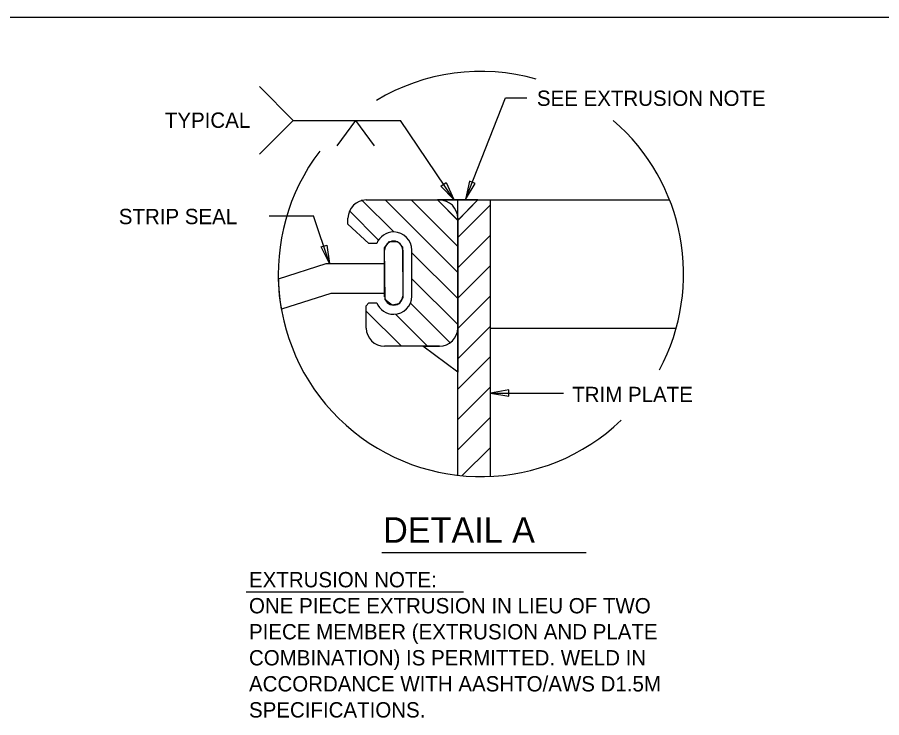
# Model space of a CAD drawing. Extents: x -24512 to -22484, y 4569 to 6351.
# Drawn here: x -23765.7 to -23596.4, y 5603.4 to 5740.6 of the extents above; entities that cross this region are included whole.
import ezdxf

# ---------------------------------------------------------------- set-up
doc = ezdxf.new("R2010")
doc.units = 0
for name, color, linetype in [('10', 7, 'Continuous'), ('2', 7, 'Continuous'), ('4', 7, 'Continuous'), ('9', 7, 'Continuous'), ('PLT-BNDY', 7, 'Continuous')]:
    doc.layers.add(name, color=color, linetype=linetype)

msp = doc.modelspace()

# ---------------------------------------------------------------- linework, layer by layer
at = {"layer": '10'}
for p, q in [((-23691.96, 5698.58), (-23698.29, 5704.91)), ((-23697.35, 5704.85), (-23683.02, 5704.85)), ((-23679.44, 5690.64), (-23693.65, 5704.85)), ((-23679.44, 5695.73), (-23688.56, 5704.85)), ((-23679.44, 5700.88), (-23683.42, 5704.85)), ((-23679.44, 5700.88), (-23675.47, 5704.85)), ((-23694.95, 5697.01), (-23700.64, 5702.7)), ((-23679.44, 5697.52), (-23673.05, 5703.9)), ((-23700.94, 5700.08), (-23700.94, 5701.27)), ((-23679.44, 5701.27), (-23679.44, 5679.77)), ((-23696.87, 5696.34), (-23700.94, 5700.08)), ((-23679.44, 5691.58), (-23673.05, 5697.96)), ((-23695.3, 5696.34), (-23696.87, 5696.34)), ((-23693.77, 5695.49), (-23692.79, 5696.69)), ((-23692.79, 5696.69), (-23691.26, 5696.74)), ((-23691.26, 5696.74), (-23690.23, 5695.65)), ((-23690.23, 5695.65), (-23690.18, 5685.77)), ((-23693.68, 5685.32), (-23693.77, 5695.49)), ((-23688.4, 5686.04), (-23688.4, 5695)), ((-23679.44, 5685.55), (-23688.4, 5694.51)), ((-23714.57, 5689.41), (-23705.18, 5692.4)), ((-23705.18, 5692.4), (-23693.77, 5692.4)), ((-23693.77, 5692.4), (-23693.77, 5686.52)), ((-23679.44, 5685.64), (-23673.05, 5692.03)), ((-23679.44, 5680.46), (-23688.4, 5689.42)), ((-23704.26, 5686.52), (-23713.97, 5683.43)), ((-23693.77, 5686.52), (-23704.26, 5686.52)), ((-23690.18, 5685.77), (-23690.98, 5684.48)), ((-23679.44, 5679.7), (-23673.05, 5686.09)), ((-23697.35, 5684.1), (-23696.87, 5684.7)), ((-23697.35, 5679.77), (-23697.35, 5684.1)), ((-23696.87, 5684.7), (-23695.3, 5684.7)), ((-23692.26, 5684.26), (-23693.68, 5685.32)), ((-23690.98, 5684.48), (-23692.26, 5684.26)), ((-23680.93, 5676.86), (-23688.69, 5684.62)), ((-23690.44, 5676.19), (-23697.35, 5683.1)), ((-23685.35, 5676.19), (-23691.64, 5682.48)), ((-23679.44, 5673.76), (-23673.05, 5680.15)), ((-23679.44, 5679.77), (-23679.44, 5671.12)), ((-23683.02, 5676.19), (-23693.77, 5676.19)), ((-23679.44, 5671.12), (-23686.24, 5676.19)), ((-23686.24, 5676.19), (-23683.02, 5676.19)), ((-23679.44, 5667.82), (-23673.05, 5674.21)), ((-23679.44, 5661.88), (-23673.05, 5668.27)), ((-23679.44, 5655.94), (-23673.05, 5662.33)), ((-23678.6, 5650.84), (-23673.05, 5656.39)), ((-23654.31, 5635.73), (-23694.31, 5635.73)), ((-23678.29, 5628.02), (-23720.86, 5628.02))]:
    msp.add_line(p, q, dxfattribs=at)
msp.add_lwpolyline([(-23713.97, 5683.43), (-23714.35, 5686.17), (-23714.57, 5689.41)], dxfattribs=at)
for centre, radius, start, end in [((-23674.89, 5690.36), 39.69, 74.1716, 121.062), ((-23674.89, 5690.36), 39.69, 331.7898, 49.227), ((-23674.89, 5690.36), 39.69, 142.6924, 313.8219), ((-23697.35, 5701.27), 3.58, 90, 180), ((-23683.02, 5701.27), 3.58, 0, 90), ((-23691.98, 5695), 3.58, 90, 157.9967), ((-23691.98, 5695), 3.58, 0, 90), ((-23691.98, 5686.04), 3.58, 270, 0), ((-23691.98, 5686.04), 3.58, 202.0033, 270), ((-23693.77, 5679.77), 3.58, 180, 270), ((-23683.02, 5679.77), 3.58, 270, 0), ((-23683.02, 5679.77), 3.58, 270, 0)]:
    msp.add_arc(centre, radius, start, end, dxfattribs=at)
at = {"layer": '2'}
msp.add_line((-24137.79, 5740.63), (-23353.75, 5740.63), dxfattribs=at)
at = {"layer": '4'}
for p, q in [((-23684.66, 5704.85), (-23676.71, 5704.85)), ((-23679.44, 5650.93), (-23679.44, 5704.85)), ((-23679.44, 5704.85), (-23637.94, 5704.85)), ((-23673.05, 5650.71), (-23673.05, 5704.85)), ((-23673.05, 5679.77), (-23636.63, 5679.77))]:
    msp.add_line(p, q, dxfattribs=at)
msp.add_lwpolyline([(-23683.42, 5704.85), (-23679.43, 5700.86), (-23675.47, 5704.85)], close=True, dxfattribs=at)
at = {"layer": '9'}
for p, q in [((-23718.28, 5727.06), (-23711.66, 5720.44)), ((-23677.94, 5704.94), (-23670.11, 5724.84)), ((-23670.11, 5724.84), (-23665.93, 5724.84)), ((-23718.28, 5713.82), (-23711.66, 5720.44)), ((-23711.66, 5720.44), (-23690.67, 5720.44)), ((-23703.02, 5715.45), (-23699.37, 5720.44)), ((-23695.72, 5715.45), (-23699.37, 5720.44)), ((-23680.2, 5704.94), (-23690.67, 5720.44)), ((-23716.37, 5701.75), (-23707.66, 5701.75)), ((-23704.53, 5692.4), (-23707.66, 5701.75)), ((-23673.05, 5667.04), (-23658.69, 5667.04))]:
    msp.add_line(p, q, dxfattribs=at)
for points in [[(-23682.72, 5707.58), (-23681.73, 5708.26), (-23680.2, 5704.94)], [(-23676.05, 5708.07), (-23677.16, 5708.51), (-23677.94, 5704.94)], [(-23706.21, 5695.64), (-23705.07, 5696.01), (-23704.53, 5692.4)], [(-23669.45, 5666.44), (-23669.45, 5667.64), (-23673.05, 5667.04)]]:
    msp.add_lwpolyline(points, close=True, dxfattribs=at)
at = {"layer": 'PLT-BNDY'}
for p, q in [((-23693.77, 5685.91), (-23693.77, 5695)), ((-23690.19, 5695), (-23690.19, 5686.04))]:
    msp.add_line(p, q, dxfattribs=at)
for centre, start, end in [((-23691.98, 5695), 90, 180), ((-23691.98, 5695), 0, 90), ((-23691.98, 5686.04), 180, 270), ((-23691.98, 5686.04), 270, 0)]:
    msp.add_arc(centre, 1.79, start, end, dxfattribs=at)

# ---------------------------------------------------------------- texts
at = {"layer": '9'}
for s, height, p in [('SEE EXTRUSION NOTE', 2.9999, (-23663.93, 5723.28)), ('TYPICAL', 3, (-23736.8, 5718.98)), ('STRIP SEAL', 3, (-23745.82, 5700.11)), ('TRIM PLATE', 3, (-23657.01, 5665.25)), ('DETAIL A', 5, (-23694.04, 5637.71)), ('EXTRUSION NOTE:', 2.9999, (-23720.32, 5628.98)), ('ONE PIECE EXTRUSION IN LIEU OF TWO ', 2.9999, (-23720.32, 5623.88)), ('PIECE MEMBER (EXTRUSION AND PLATE', 2.9999, (-23720.32, 5618.78)), ('COMBINATION) IS PERMITTED. WELD IN ', 2.9999, (-23720.32, 5613.68)), ('ACCORDANCE WITH AASHTO/AWS D1.5M', 2.9999, (-23720.32, 5608.58)), ('SPECIFICATIONS.', 2.9999, (-23720.32, 5603.48))]:
    msp.add_text(s, height=height, dxfattribs=at).set_placement(p)

doc.saveas('drawing.dxf')
